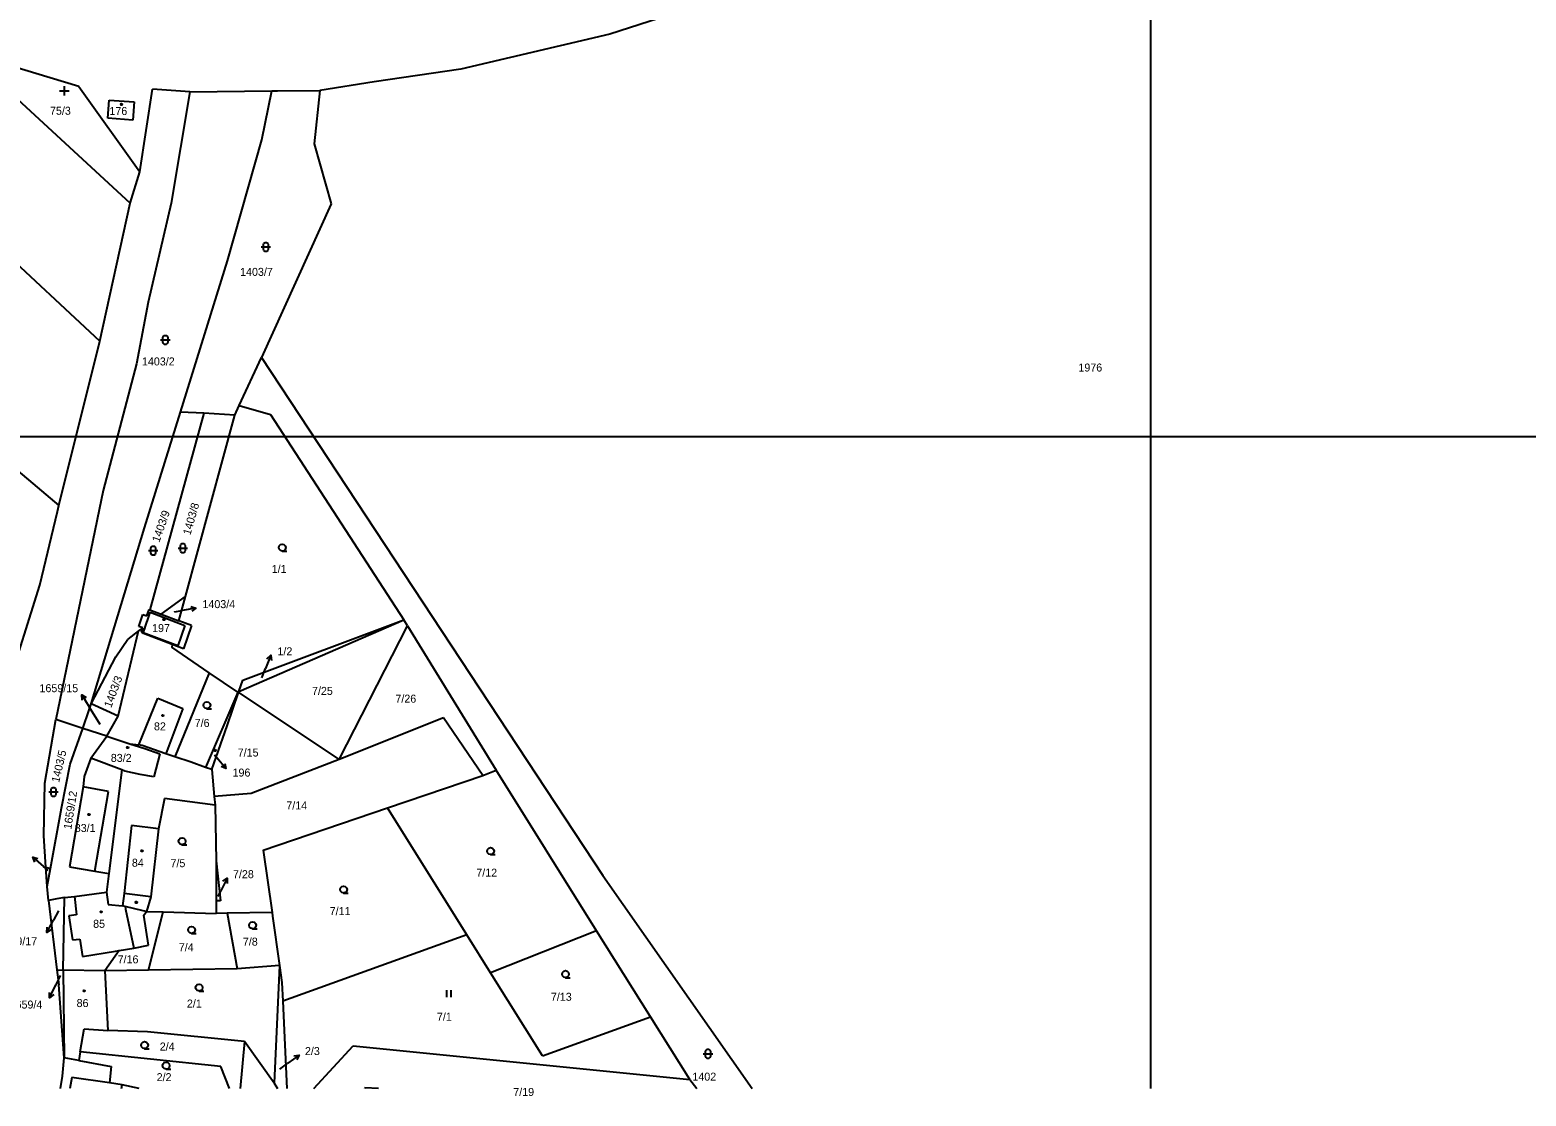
# Model space of a CAD drawing. Extents: x -801853 to -800578, y -1017479 to -1016338.
# Drawn here: x -801488.1 to -801170.2, y -1017479.3 to -1017252.6 of the extents above; entities that cross this region are included whole.
import ezdxf

# ---------------------------------------------------------------- set-up
doc = ezdxf.new("R2010")
doc.units = 0
for name, color, linetype in [('Default', 7, 'Continuous'), ('KLADY_ZMVM', 7, 'Continuous'), ('KN_HRANICE', 7, 'Continuous'), ('KN_KULTURY', 7, 'Continuous'), ('KN_PARCELY', 7, 'Continuous'), ('KN_SLUCKY', 7, 'Continuous'), ('LEGENDA', 7, 'Continuous')]:
    doc.layers.add(name, color=color, linetype=linetype)

# ---------------------------------------------------------------- blocks, each defined once
blk = doc.blocks.new('304')
at = {"layer": 'Default'}
blk.add_lwpolyline([(0, 0), (-0.38, 0.1), (-0.65, 0.37), (-0.75, 0.74), (-0.65, 1.11), (-0.38, 1.38), (-0.01, 1.48), (0.36, 1.38), (0.63, 1.11), (0.73, 0.73), (0.63, 0.35), (0.36, 0.08), (-0.02, -0.02), (0.98, -0.02)], dxfattribs=at)
blk = doc.blocks.new('306')
at = {"layer": 'Default'}
for p, q in [((-0.5, 1.5), (-0.5, 0)), ((0.5, 0), (0.5, 1.5))]:
    blk.add_line(p, q, dxfattribs=at)
blk = doc.blocks.new('315')
at = {"layer": 'Default'}
for p, q in [((-1, 1), (1, 1)), ((0, 0), (0, 2))]:
    blk.add_line(p, q, dxfattribs=at)
blk = doc.blocks.new('316')
at = {"layer": 'Default'}
for points in [[(-1, 1), (0.27, 1), (1, 1)], [(-0.5, 1.5), (-0.4, 1.79), (-0.15, 1.97), (0.16, 1.97), (0.41, 1.79), (0.51, 1.5), (0.51, 0.5), (0.41, 0.21), (0.16, 0.03), (-0.15, 0.03), (-0.4, 0.21), (-0.5, 0.5), (-0.5, 1.5)]]:
    blk.add_lwpolyline(points, dxfattribs=at)
blk = doc.blocks.new('NAHRADNI_SYMBOL')
at = {"layer": 'Default'}
blk.add_lwpolyline([(0.09, 0.15), (0.18, 0), (0.09, -0.15), (-0.09, -0.15), (-0.18, 0), (-0.09, 0.15), (0.09, 0.15)], dxfattribs=at)
blk = doc.blocks.new('10292')
at = {"layer": 'Default'}
blk.add_line((0, 3), (0, 0), dxfattribs=at)
blk.add_lwpolyline([(-0.5, 2), (0, 3), (0.5, 2)], dxfattribs=at)
blk = doc.blocks.new('402')
at = {"layer": 'Default'}
blk.add_lwpolyline([(0.09, 0.15), (0.18, 0), (0.09, -0.15), (-0.09, -0.15), (-0.18, 0), (-0.09, 0.15), (0.09, 0.15)], dxfattribs=at)

msp = doc.modelspace()

# ---------------------------------------------------------------- linework, layer by layer
at = {"layer": 'KLADY_ZMVM'}
msp.add_lwpolyline([(-801250, -1017000), (-801250, -1017477.65)], dxfattribs=at)
at = {"layer": 'KN_HRANICE'}
for p, q in [((-801619.51, -1017238.39), (-801481.95, -1017353.71)), ((-801318.92, -1017238.69), (-801364.93, -1017253.53)), ((-801364.93, -1017253.53), (-801396.54, -1017260.97)), ((-801477.73, -1017264.63), (-801501.56, -1017257.45)), ((-801466.82, -1017289.45), (-801501.56, -1017257.45)), ((-801396.54, -1017260.97), (-801415.01, -1017263.64)), ((-801477.73, -1017264.63), (-801464.79, -1017282.78)), ((-801464.79, -1017282.78), (-801462.07, -1017265.26)), ((-801454.13, -1017265.82), (-801462.07, -1017265.26)), ((-801415.01, -1017263.64), (-801426.49, -1017265.49)), ((-801471.6, -1017271.43), (-801471.3, -1017267.55)), ((-801471.3, -1017267.55), (-801466, -1017267.95)), ((-801466, -1017267.95), (-801466.29, -1017271.83)), ((-801454.13, -1017265.82), (-801458.15, -1017289.48)), ((-801454.13, -1017265.82), (-801436.73, -1017265.61)), ((-801438.87, -1017276.02), (-801436.73, -1017265.61)), ((-801436.73, -1017265.61), (-801435.52, -1017265.6)), ((-801435.52, -1017265.6), (-801426.49, -1017265.49)), ((-801426.49, -1017265.49), (-801427.72, -1017276.85)), ((-801466.29, -1017271.83), (-801471.6, -1017271.43)), ((-801473.28, -1017318.78), (-801518.94, -1017276.33)), ((-801446.14, -1017301.75), (-801438.87, -1017276.02)), ((-801427.72, -1017276.85), (-801424.14, -1017289.58)), ((-801466.82, -1017289.45), (-801464.79, -1017282.78)), ((-801473.28, -1017318.78), (-801466.82, -1017289.45)), ((-801458.15, -1017289.48), (-801462.97, -1017310.53)), ((-801424.14, -1017289.58), (-801438.92, -1017322.27)), ((-801456.12, -1017333.87), (-801446.14, -1017301.75)), ((-801462.97, -1017310.53), (-801465.45, -1017323.65)), ((-801481.95, -1017353.71), (-801473.28, -1017318.78)), ((-801443.65, -1017332.48), (-801438.92, -1017322.27)), ((-801438.92, -1017322.27), (-801366.39, -1017432.38)), ((-801465.45, -1017323.65), (-801472.56, -1017350.57)), ((-801463.78, -1017358.51), (-801456.12, -1017333.87)), ((-801451.19, -1017334.14), (-801462.64, -1017375.93)), ((-801451.19, -1017334.14), (-801456.12, -1017333.87)), ((-801455.08, -1017373.05), (-801444.59, -1017334.5)), ((-801444.59, -1017334.5), (-801451.19, -1017334.14)), ((-801444.59, -1017334.5), (-801443.65, -1017332.48)), ((-801443.65, -1017332.48), (-801437.03, -1017334.42)), ((-801437.03, -1017334.42), (-801408.69, -1017378.05)), ((-801472.56, -1017350.57), (-801482.61, -1017399.26)), ((-801482.28, -1017355.03), (-801481.95, -1017353.71)), ((-801486.04, -1017370.69), (-801482.28, -1017355.03)), ((-801475.12, -1017395.87), (-801463.78, -1017358.51)), ((-801493.03, -1017393.07), (-801486.04, -1017370.69)), ((-801460.21, -1017376.86), (-801455.08, -1017373.05)), ((-801456.5, -1017378.26), (-801455.08, -1017373.05)), ((-801463.26, -1017377.18), (-801462.81, -1017375.87)), ((-801462.81, -1017375.87), (-801462.64, -1017375.93)), ((-801462.64, -1017375.93), (-801460.21, -1017376.86)), ((-801464.14, -1017379.72), (-801465.04, -1017380.4)), ((-801464.99, -1017379.43), (-801464.11, -1017376.89)), ((-801464.14, -1017379.72), (-801464.99, -1017379.43)), ((-801464.45, -1017380.63), (-801464.14, -1017379.72)), ((-801464.11, -1017376.89), (-801463.26, -1017377.18)), ((-801460.21, -1017376.86), (-801456.5, -1017378.26)), ((-801453.76, -1017379.27), (-801456.5, -1017378.26)), ((-801453.76, -1017379.27), (-801455.47, -1017384.17)), ((-801443.73, -1017393.29), (-801408.69, -1017378.05)), ((-801442.91, -1017390.9), (-801408.69, -1017378.05)), ((-801422.42, -1017407.74), (-801407.88, -1017379.29)), ((-801407.88, -1017379.29), (-801408.69, -1017378.05)), ((-801407.88, -1017379.29), (-801389.06, -1017410.03)), ((-801469.88, -1017385.9), (-801467.33, -1017382.12)), ((-801469.37, -1017398.55), (-801465.04, -1017380.4)), ((-801465.04, -1017380.4), (-801467.33, -1017382.12)), ((-801464.01, -1017380.93), (-801464.45, -1017380.63)), ((-801457.88, -1017383.3), (-801464.01, -1017380.93)), ((-801475.12, -1017395.87), (-801469.88, -1017385.9)), ((-801457.88, -1017383.3), (-801458, -1017383.82)), ((-801450.03, -1017389.33), (-801458, -1017383.82)), ((-801455.47, -1017384.17), (-801457.88, -1017383.3)), ((-801450.03, -1017389.33), (-801457.32, -1017407.16)), ((-801443.97, -1017393.39), (-801450.03, -1017389.33)), ((-801443.73, -1017393.29), (-801442.91, -1017390.9)), ((-801443.97, -1017393.39), (-801450.79, -1017409.43)), ((-801446.23, -1017400.56), (-801443.8, -1017393.5)), ((-801443.97, -1017393.39), (-801443.73, -1017393.29)), ((-801443.8, -1017393.5), (-801443.73, -1017393.29)), ((-801443.8, -1017393.5), (-801422.42, -1017407.74)), ((-801476.91, -1017401.11), (-801475.51, -1017397.16)), ((-801475.51, -1017397.16), (-801475.12, -1017395.87)), ((-801469.37, -1017398.55), (-801475.12, -1017395.87)), ((-801471.82, -1017402.77), (-801469.37, -1017398.55)), ((-801400.24, -1017398.84), (-801422.42, -1017407.74)), ((-801391.91, -1017411.13), (-801400.24, -1017398.84)), ((-801484.97, -1017412.74), (-801482.61, -1017399.26)), ((-801476.91, -1017401.11), (-801482.61, -1017399.26)), ((-801479.6, -1017408.7), (-801476.91, -1017401.11)), ((-801471.82, -1017402.77), (-801476.91, -1017401.11)), ((-801449.49, -1017409.89), (-801446.23, -1017400.56)), ((-801475.18, -1017407.42), (-801471.82, -1017402.77)), ((-801471.82, -1017402.77), (-801466.9, -1017404.38)), ((-801466.9, -1017404.38), (-801463.71, -1017405.36)), ((-801466.9, -1017404.38), (-801464.99, -1017404.58)), ((-801464.3, -1017404.78), (-801464.99, -1017404.58)), ((-801459.24, -1017406.5), (-801464.3, -1017404.78)), ((-801475.18, -1017407.42), (-801476.57, -1017411.34)), ((-801468.57, -1017409.95), (-801475.18, -1017407.42)), ((-801463.71, -1017405.36), (-801460.5, -1017406.5)), ((-801460.5, -1017406.5), (-801461.81, -1017411.42)), ((-801457.32, -1017407.16), (-801459.24, -1017406.5)), ((-801453.89, -1017408.33), (-801457.32, -1017407.16)), ((-801450.79, -1017409.43), (-801453.89, -1017408.33)), ((-801422.42, -1017407.74), (-801441.13, -1017414.93)), ((-801481.43, -1017418.11), (-801479.6, -1017408.7)), ((-801476.57, -1017411.34), (-801476.78, -1017413.57)), ((-801468.57, -1017409.95), (-801471.37, -1017431.95)), ((-801467.94, -1017410.19), (-801468.57, -1017409.95)), ((-801464.69, -1017410.9), (-801467.94, -1017410.19)), ((-801461.81, -1017411.42), (-801464.69, -1017410.9)), ((-801449.49, -1017409.89), (-801450.79, -1017409.43)), ((-801449.49, -1017409.89), (-801448.95, -1017415.59)), ((-801412.18, -1017418.02), (-801391.91, -1017411.13)), ((-801391.91, -1017411.13), (-801389.06, -1017410.03)), ((-801367.72, -1017444.15), (-801389.06, -1017410.03)), ((-801485.18, -1017423.98), (-801484.97, -1017412.74)), ((-801476.78, -1017413.57), (-801479.73, -1017430.52)), ((-801459.51, -1017416.03), (-801460.82, -1017422.5)), ((-801448.78, -1017417.45), (-801459.51, -1017416.03)), ((-801441.13, -1017414.93), (-801448.95, -1017415.59)), ((-801448.95, -1017415.59), (-801448.78, -1017417.45)), ((-801448.78, -1017417.45), (-801448.56, -1017429.24)), ((-801483.75, -1017430.88), (-801481.43, -1017418.11)), ((-801438.55, -1017426.97), (-801412.18, -1017418.02)), ((-801395.3, -1017445.02), (-801412.18, -1017418.02)), ((-801484.77, -1017430.63), (-801485.18, -1017423.98)), ((-801460.82, -1017422.5), (-801462.42, -1017436.96)), ((-801438.55, -1017426.97), (-801436.67, -1017440.26)), ((-801484.44, -1017434.71), (-801484.77, -1017430.63)), ((-801484.77, -1017430.63), (-801483.75, -1017430.88)), ((-801479.73, -1017430.52), (-801474.31, -1017431.46)), ((-801448.56, -1017429.24), (-801447.64, -1017437.77)), ((-801448.56, -1017429.24), (-801448.55, -1017437.77)), ((-801484.44, -1017434.71), (-801483.75, -1017430.88)), ((-801474.31, -1017431.46), (-801471.37, -1017431.95)), ((-801471.37, -1017431.95), (-801471.88, -1017435.96)), ((-801366.39, -1017432.38), (-801334.68, -1017477.65)), ((-801484.2, -1017437.73), (-801484.44, -1017434.71)), ((-801480.79, -1017437.04), (-801482.44, -1017437.37)), ((-801481.05, -1017452.5), (-801480.79, -1017437.04)), ((-801480.79, -1017437.04), (-801478.66, -1017436.87)), ((-801478.66, -1017436.87), (-801471.88, -1017435.96)), ((-801471.88, -1017435.96), (-801471.48, -1017438.57)), ((-801462.42, -1017436.96), (-801463.38, -1017440.03)), ((-801482.44, -1017437.37), (-801484.2, -1017437.73)), ((-801484.2, -1017437.73), (-801482.44, -1017452.42)), ((-801471.48, -1017438.57), (-801468.43, -1017438.86)), ((-801467.91, -1017438.98), (-801468.43, -1017438.86)), ((-801464.08, -1017439.87), (-801467.91, -1017438.98)), ((-801463.38, -1017440.03), (-801464.08, -1017439.87)), ((-801463.93, -1017440.81), (-801463.38, -1017440.03)), ((-801463.38, -1017440.03), (-801459.78, -1017440.14)), ((-801462.91, -1017452.5), (-801459.78, -1017440.14)), ((-801459.78, -1017440.14), (-801448.54, -1017440.47)), ((-801447.64, -1017437.77), (-801448.55, -1017437.77)), ((-801448.55, -1017437.77), (-801448.54, -1017440.47)), ((-801436.67, -1017440.26), (-801446.24, -1017440.43)), ((-801436.67, -1017440.26), (-801436.56, -1017441.04)), ((-801462.92, -1017447.17), (-801463.93, -1017440.81)), ((-801446.24, -1017440.43), (-801448.54, -1017440.47)), ((-801446.24, -1017440.43), (-801444.06, -1017452.22)), ((-801436.56, -1017441.04), (-801435.08, -1017451.54)), ((-801395.3, -1017445.02), (-801434.42, -1017459.09)), ((-801390.25, -1017453.11), (-801395.3, -1017445.02)), ((-801367.72, -1017444.15), (-801390.25, -1017453.11)), ((-801356.25, -1017462.47), (-801367.72, -1017444.15)), ((-801469.2, -1017448.34), (-801472.2, -1017452.64)), ((-801469.2, -1017448.34), (-801466.08, -1017447.84)), ((-801466.08, -1017447.84), (-801462.92, -1017447.17)), ((-801482.44, -1017452.42), (-801481.05, -1017452.5)), ((-801482.44, -1017452.42), (-801481.99, -1017455.66)), ((-801472.2, -1017452.64), (-801481.05, -1017452.5)), ((-801481.05, -1017452.5), (-801480.85, -1017471.15)), ((-801462.91, -1017452.5), (-801472.2, -1017452.64)), ((-801472.2, -1017452.64), (-801471.55, -1017465.31)), ((-801444.06, -1017452.22), (-801462.91, -1017452.5)), ((-801435.08, -1017451.54), (-801444.06, -1017452.22)), ((-801435.08, -1017451.54), (-801436.26, -1017476.56)), ((-801435.08, -1017451.54), (-801434.61, -1017455.17)), ((-801480.85, -1017471.15), (-801481.99, -1017455.66)), ((-801434.61, -1017455.17), (-801434.42, -1017459.09)), ((-801379.24, -1017470.71), (-801390.25, -1017453.11)), ((-801434.42, -1017459.09), (-801433.51, -1017477.65)), ((-801379.24, -1017470.71), (-801356.25, -1017462.47)), ((-801347.93, -1017475.78), (-801356.25, -1017462.47)), ((-801477.42, -1017469.86), (-801476.6, -1017465.01)), ((-801476.6, -1017465.01), (-801471.55, -1017465.31)), ((-801463.11, -1017465.64), (-801471.55, -1017465.31)), ((-801442.53, -1017467.71), (-801463.11, -1017465.64)), ((-801442.53, -1017467.71), (-801443.44, -1017477.65)), ((-801436.26, -1017476.56), (-801442.53, -1017467.71)), ((-801427.81, -1017477.65), (-801419.41, -1017468.61)), ((-801419.41, -1017468.61), (-801347.93, -1017475.78)), ((-801481.2, -1017475.07), (-801480.85, -1017471.15)), ((-801477.74, -1017471.72), (-801480.85, -1017471.15)), ((-801477.42, -1017469.86), (-801477.74, -1017471.72)), ((-801477.74, -1017471.72), (-801470.85, -1017473.01)), ((-801447.58, -1017472.97), (-801477.42, -1017469.86)), ((-801481.66, -1017477.65), (-801481.2, -1017475.07)), ((-801470.85, -1017473.01), (-801471.25, -1017476.47)), ((-801445.72, -1017477.65), (-801447.58, -1017472.97)), ((-801468.51, -1017476.86), (-801471.25, -1017476.47)), ((-801464.93, -1017477.65), (-801468.51, -1017476.86)), ((-801436.26, -1017476.56), (-801435.53, -1017477.65)), ((-801416.99, -1017477.52), (-801417, -1017477.65)), ((-801414.05, -1017477.65), (-801416.99, -1017477.52)), ((-801347.93, -1017475.78), (-801346.4, -1017477.65))]:
    msp.add_line(p, q, dxfattribs=at)
at = {"layer": 'KN_PARCELY'}
for p, q in [((-801457.41, -1017376.35), (-801455.81, -1017376.07)), ((-801438.84, -1017390.35), (-801438.04, -1017388.36)), ((-801473.22, -1017400.28), (-801475.54, -1017396.53)), ((-801448.9, -1017406.77), (-801448.4, -1017407.37)), ((-801484.27, -1017431.32), (-801485.23, -1017430.49)), ((-801448.16, -1017436.83), (-801447.56, -1017435.64)), ((-801482.04, -1017439.87), (-801483.1, -1017441.87)), ((-801481.69, -1017453.66), (-801482.65, -1017455.66)), ((-801435.04, -1017473.53), (-801433.36, -1017472.32))]:
    msp.add_line(p, q, dxfattribs=at)
at = {"layer": 'KN_SLUCKY'}
for p, q in [((-801462.86, -1017377.32), (-801462.55, -1017376.41)), ((-801462.55, -1017376.41), (-801455.19, -1017379.23)), ((-801464.05, -1017380.77), (-801463.74, -1017379.86)), ((-801463.74, -1017379.86), (-801463.58, -1017379.36)), ((-801463.58, -1017379.36), (-801462.86, -1017377.32)), ((-801455.19, -1017379.23), (-801456.68, -1017383.56)), ((-801456.68, -1017383.56), (-801464.05, -1017380.77)), ((-801464.99, -1017404.58), (-801460.92, -1017394.66)), ((-801460.92, -1017394.66), (-801455.63, -1017396.89)), ((-801455.63, -1017396.89), (-801459.24, -1017406.5)), ((-801471.46, -1017414.5), (-801476.78, -1017413.57)), ((-801474.31, -1017431.46), (-801471.46, -1017414.5)), ((-801466.53, -1017421.73), (-801468.13, -1017436.19)), ((-801460.82, -1017422.5), (-801466.53, -1017421.73)), ((-801478.66, -1017436.87), (-801478.26, -1017440.73)), ((-801468.13, -1017436.19), (-801468.43, -1017438.86)), ((-801462.42, -1017436.96), (-801468.13, -1017436.19)), ((-801467.91, -1017438.98), (-801467.8, -1017439.52)), ((-801467.8, -1017439.52), (-801466.08, -1017447.84)), ((-801478.26, -1017440.73), (-801479.84, -1017440.98)), ((-801479.84, -1017440.98), (-801479.1, -1017446.07)), ((-801479.1, -1017446.07), (-801477.5, -1017445.91)), ((-801477.5, -1017445.91), (-801476.98, -1017449.6)), ((-801476.98, -1017449.6), (-801469.95, -1017448.47)), ((-801469.95, -1017448.47), (-801469.2, -1017448.34)), ((-801479.23, -1017475.34), (-801479.64, -1017477.65)), ((-801471.25, -1017476.47), (-801479.23, -1017475.34)), ((-801468.7, -1017477.65), (-801468.51, -1017476.86))]:
    msp.add_line(p, q, dxfattribs=at)
at = {"layer": 'LEGENDA'}
msp.add_lwpolyline([(-801559.16, -1017339.08), (-800718.16, -1017339.08), (-800718.16, -1016745.08), (-801559.16, -1016745.08)], close=True, dxfattribs=at)

# ---------------------------------------------------------------- block references
at = {"layer": 'KN_KULTURY'}
for name, p in [('315', (-801480.81, -1017266.56)), ('402', (-801468.66, -1017268.45)), ('316', (-801438.02, -1017299.77)), ('316', (-801459.36, -1017319.54)), ('316', (-801461.92, -1017364.33)), ('316', (-801455.63, -1017363.81)), ('304', (-801434.51, -1017363.42)), ('402', (-801459.63, -1017377.97)), ('304', (-801450.51, -1017396.92)), ('402', (-801459.9, -1017398.39)), ('402', (-801467.35, -1017405.18)), ('NAHRADNI_SYMBOL', (-801448.77, -1017405.79)), ('316', (-801483.13, -1017415.62)), ('402', (-801475.59, -1017419.42)), ('304', (-801455.8, -1017425.84)), ('402', (-801464.3, -1017427.17)), ('304', (-801390.23, -1017427.94)), ('304', (-801421.48, -1017436.11)), ('402', (-801472.99, -1017440.12)), ('402', (-801465.5, -1017438.1)), ('304', (-801453.78, -1017444.69)), ('304', (-801440.79, -1017443.71)), ('304', (-801374.31, -1017454.09)), ('304', (-801452.18, -1017456.94)), ('NAHRADNI_SYMBOL', (-801476.59, -1017456.92)), ('306', (-801399.14, -1017458.26)), ('304', (-801463.74, -1017469.19)), ('316', (-801344.05, -1017471.3)), ('304', (-801459.19, -1017473.55))]:
    msp.add_blockref(name, p, dxfattribs=at)
at = {"layer": 'KN_PARCELY'}
for p, rotation in [((-801455.81, -1017376.07), -80.05282100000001), ((-801438.04, -1017388.36), -21.897605), ((-801475.54, -1017396.53), 31.741862), ((-801448.4, -1017407.37), -139.81231900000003), ((-801485.23, -1017430.49), 49.15977900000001), ((-801447.56, -1017435.64), -26.595858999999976), ((-801483.1, -1017441.87), 152.005703), ((-801482.65, -1017455.66), 154.469422), ((-801433.36, -1017472.32), -54.155129)]:
    msp.add_blockref('10292', p, dxfattribs=dict(at, rotation=rotation))

# ---------------------------------------------------------------- texts
for s, height, p in [('75/3', 1.7, (-801483.86, -1017270.67)), ('176', 1.7, (-801471.24, -1017270.72)), ('1403/7', 1.7, (-801443.47, -1017304.92)), ('1403/2', 1.7, (-801464.32, -1017323.96)), ('1976', 1.7, (-801265.34, -1017325.26)), ('1/1', 1.7, (-801436.75, -1017368.08)), ('1403/4', 0.1, (-801457.71, -1017376.35)), ('1403/4', 1.7, (-801451.47, -1017375.55)), ('197', 1.7, (-801462.17, -1017380.64)), ('1/2', 1.7, (-801435.53, -1017385.58)), ('1659/15', 1.7, (-801486.1, -1017393.42)), ('1/2', 0.1, (-801438.99, -1017390.35)), ('7/25', 1.7, (-801428.19, -1017394)), ('7/26', 1.7, (-801410.47, -1017395.65)), ('1659/15', 0.1, (-801473.57, -1017400.28)), ('82', 1.7, (-801461.77, -1017401.54)), ('7/6', 1.7, (-801453.12, -1017400.81)), ('83/2', 1.7, (-801470.94, -1017408.24)), ('196', 0.1, (-801449.05, -1017406.77)), ('7/15', 1.7, (-801443.97, -1017407.1)), ('196', 1.7, (-801445.07, -1017411.36)), ('7/14', 1.7, (-801433.65, -1017418.35)), ('83/1', 1.7, (-801478.6, -1017423.14)), ('84', 1.7, (-801466.46, -1017430.53)), ('7/5', 1.7, (-801458.26, -1017430.62)), ('1403/6', 0.1, (-801484.57, -1017431.32)), ('7/28', 1.7, (-801444.98, -1017432.96)), ('7/12', 1.7, (-801393.28, -1017432.64)), ('7/28', 0.1, (-801448.36, -1017436.83)), ('1659/17', 0.1, (-801482.39, -1017439.87)), ('7/11', 1.7, (-801424.43, -1017440.81)), ('85', 1.7, (-801474.7, -1017443.51)), ('1659/17', 1.7, (-801494.8, -1017447.21)), ('7/8', 1.7, (-801442.88, -1017447.3)), ('7/16', 1.7, (-801469.49, -1017451.06)), ('7/4', 1.7, (-801456.5, -1017448.5)), ('1659/4', 0.1, (-801481.99, -1017453.66)), ('1659/4', 1.7, (-801492.44, -1017460.67)), ('86', 1.7, (-801478.21, -1017460.36)), ('2/1', 1.7, (-801454.77, -1017460.46)), ('7/13', 1.7, (-801377.43, -1017459.02)), ('7/1', 1.7, (-801401.65, -1017463.26)), ('2/4', 1.7, (-801460.54, -1017469.6)), ('2/3', 1.7, (-801429.69, -1017470.56)), ('2/2', 1.7, (-801461.2, -1017476.11)), ('2/3', 0.1, (-801435.19, -1017473.53)), ('1402', 1.7, (-801347.36, -1017476)), ('7/19', 1.7, (-801385.42, -1017479.26))]:
    msp.add_text(s, height=height, dxfattribs=at).set_placement(p)
for s, rotation, p in [('1403/8', 74.141, (-801454.03, -1017360.14)), ('1403/9', 70.703, (-801460.64, -1017361.7)), ('1403/3', 69.614, (-801470.86, -1017396.86)), ('1403/5', 76.834, (-801481.93, -1017412.74)), ('1659/12', 81.245, (-801479.33, -1017422.67))]:
    msp.add_text(s, height=1.7, rotation=rotation, dxfattribs=at).set_placement(p)

doc.saveas('drawing.dxf')
